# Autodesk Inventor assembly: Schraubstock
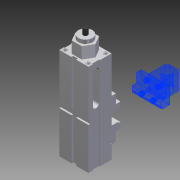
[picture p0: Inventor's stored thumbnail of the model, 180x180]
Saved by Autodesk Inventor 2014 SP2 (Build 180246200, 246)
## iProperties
Created: 2015-06
Part Number: Schraubstock
Document SubType Name: Assembly
Designer: e_krauts
Sending System: SolidWorks 2011
Last Author: e_boekem
Author: e_krauts
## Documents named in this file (6)
- C:\SolidCAM_Temp\NADELHALTER_OBEN\Schraubstock.iam
- C:\SolidCAM_Temp\NADELHALTER_OBEN\Backe20x40.ipt
- C:\SolidCAM_Temp\NADELHALTER_OBEN\Unterteil.ipt
- C:\SolidCAM_Temp\NADELHALTER_OBEN\Backe 40 x 20 ohne.ipt
- C:\SolidCAM_Temp\NADELHALTER_OBEN\Spindel.ipt
- Z:\VDW-Nachwuchsstiftung Intern\Mitarbeiter Ablage\Steffen Krauth\IVCAM\Verteilerblock.ipt
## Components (5 placed, 5 different names)
1. Backe20x40:1 — Passend:2, Fluchtend:1, Passend:6, Passend:7, Fluchtend:2
2. Unterteil:1 — Passend:1, Passend:2, Passend:4, Passend:5, Fluchtend:1
3. Backe 40 x 20 ohne:1 — Passend:3, Passend:4, Passend:8
4. Spindel:2 — Passend:1, Passend:3, Passend:5
5. Verteilerblock:1 — Passend:6, Passend:7, Fluchtend:2, Passend:8
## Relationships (10: Mate 8, Flush 2)
- Passend:1 [Mate]: Unterteil:1 ↔ Spindel:2
- Passend:2 [Mate]: Backe20x40:1 ↔ Unterteil:1
- Passend:3 [Mate]: Backe 40 x 20 ohne:1 ↔ Spindel:2
- Passend:4 [Mate]: Unterteil:1 ↔ Backe 40 x 20 ohne:1
- Passend:5 [Mate]: Unterteil:1 ↔ Spindel:2
- Fluchtend:1 [Flush]: Backe20x40:1 ↔ Unterteil:1
- Passend:6 [Mate]: Backe20x40:1 ↔ Verteilerblock:1
- Passend:7 [Mate]: Backe20x40:1 ↔ Verteilerblock:1
- Fluchtend:2 [Flush]: Backe20x40:1 ↔ Verteilerblock:1
- Passend:8 [Mate]: Backe 40 x 20 ohne:1 ↔ Verteilerblock:1
